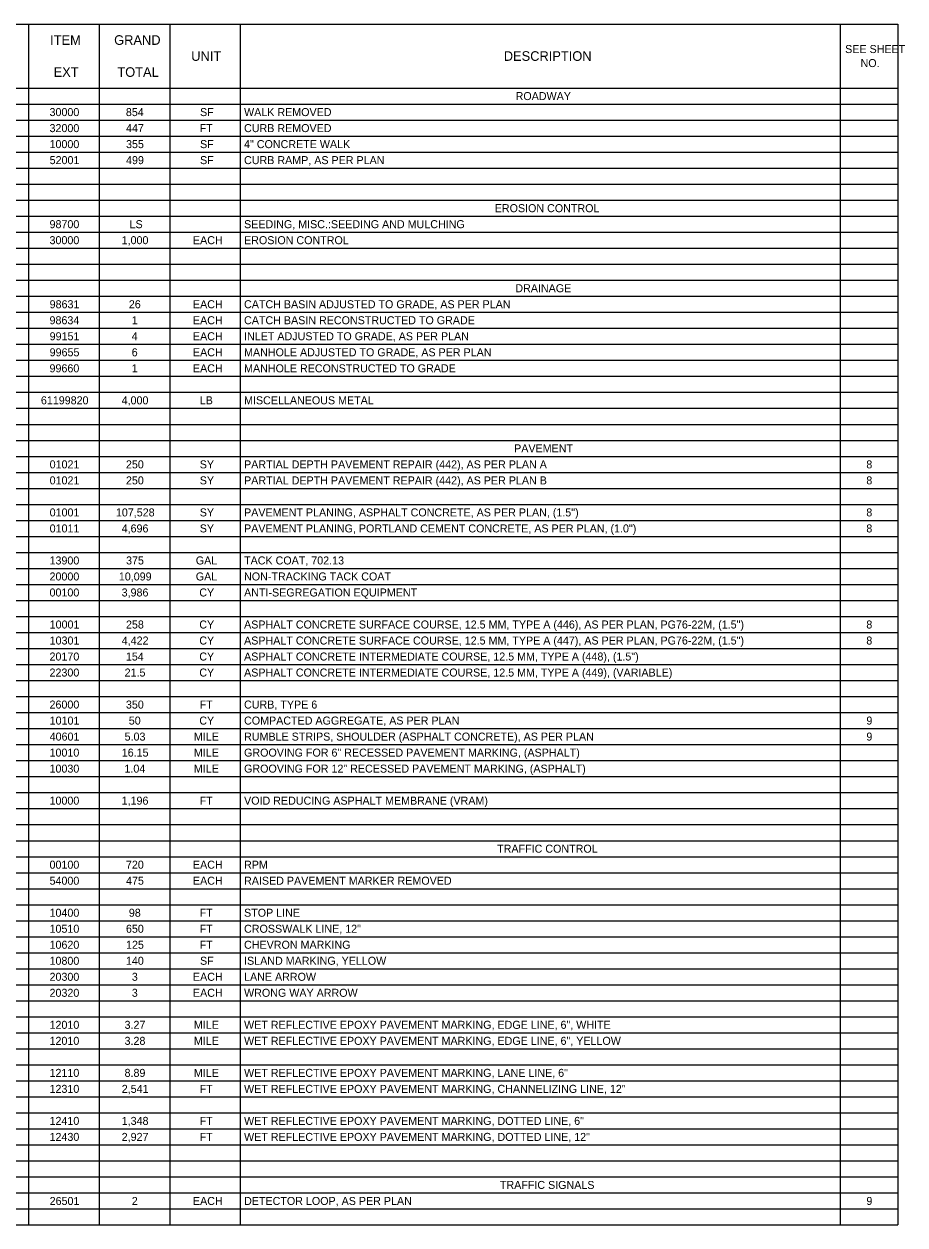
# Model space of a CAD drawing. Extents: x -32.9 to 34, y 0 to 22.
# Drawn here: x -17.72 to -2.31, y 0.5 to 21.5 of the extents above; entities that cross this region are included whole.
import ezdxf

# ---------------------------------------------------------------- set-up
doc = ezdxf.new("R2010")
doc.units = 0
doc.layers.add('SH_Text', color=7, linetype='Continuous')

msp = doc.modelspace()

# ---------------------------------------------------------------- linework, layer by layer
at = {"layer": 'SH_Text'}
for p, q in [((-32.943, 21.5), (-2.439, 21.5)), ((-17.642, 21.5), (-17.642, 0.5)), ((-16.406, 21.5), (-16.406, 0.5)), ((-15.171, 21.5), (-15.171, 0.5)), ((-13.936, 21.5), (-13.936, 0.5)), ((-3.444, 21.5), (-3.444, 0.5)), ((-2.439, 21.5), (-2.439, 0.5)), ((-32.943, 20.38), (-2.439, 20.38)), ((-32.943, 20.1), (-2.439, 20.1)), ((-32.943, 19.82), (-2.439, 19.82)), ((-32.943, 19.54), (-2.439, 19.54)), ((-32.943, 19.26), (-2.439, 19.26)), ((-32.943, 18.98), (-2.439, 18.98)), ((-32.943, 18.7), (-2.439, 18.7)), ((-32.943, 18.42), (-2.439, 18.42)), ((-32.943, 18.14), (-2.439, 18.14)), ((-32.943, 17.86), (-2.439, 17.86)), ((-32.943, 17.58), (-2.439, 17.58)), ((-32.943, 17.3), (-2.439, 17.3)), ((-32.943, 17.02), (-2.439, 17.02)), ((-32.943, 16.74), (-2.439, 16.74)), ((-32.943, 16.46), (-2.439, 16.46)), ((-32.943, 16.18), (-2.439, 16.18)), ((-32.943, 15.9), (-2.439, 15.9)), ((-32.943, 15.62), (-2.439, 15.62)), ((-32.943, 15.34), (-2.439, 15.34)), ((-32.943, 15.06), (-2.439, 15.06)), ((-32.943, 14.78), (-2.439, 14.78)), ((-32.943, 14.5), (-2.439, 14.5)), ((-32.943, 14.22), (-2.439, 14.22)), ((-32.943, 13.94), (-2.439, 13.94)), ((-32.943, 13.66), (-2.439, 13.66)), ((-32.943, 13.38), (-2.439, 13.38)), ((-32.943, 13.1), (-2.439, 13.1)), ((-32.943, 12.82), (-2.439, 12.82)), ((-32.943, 12.54), (-2.439, 12.54)), ((-32.943, 12.26), (-2.439, 12.26)), ((-32.943, 11.98), (-2.439, 11.98)), ((-32.943, 11.7), (-2.439, 11.7)), ((-32.943, 11.42), (-2.439, 11.42)), ((-32.943, 11.14), (-2.439, 11.14)), ((-32.943, 10.86), (-2.439, 10.86)), ((-32.943, 10.58), (-2.439, 10.58)), ((-32.943, 10.3), (-2.439, 10.3)), ((-32.943, 10.02), (-2.439, 10.02)), ((-32.943, 9.74), (-2.439, 9.74)), ((-32.943, 9.46), (-2.439, 9.46)), ((-32.943, 9.18), (-2.439, 9.18)), ((-32.943, 8.9), (-2.439, 8.9)), ((-32.943, 8.62), (-2.439, 8.62)), ((-32.943, 8.34), (-2.439, 8.34)), ((-32.943, 8.06), (-2.439, 8.06)), ((-32.943, 7.78), (-2.439, 7.78)), ((-32.943, 7.5), (-2.439, 7.5)), ((-32.943, 7.22), (-2.439, 7.22)), ((-32.943, 6.94), (-2.439, 6.94)), ((-32.943, 6.66), (-2.439, 6.66)), ((-32.943, 6.38), (-2.439, 6.38)), ((-32.943, 6.1), (-2.439, 6.1)), ((-32.943, 5.82), (-2.439, 5.82)), ((-32.943, 5.54), (-2.439, 5.54)), ((-32.943, 5.26), (-2.439, 5.26)), ((-32.943, 4.98), (-2.439, 4.98)), ((-32.943, 4.7), (-2.439, 4.7)), ((-32.943, 4.42), (-2.439, 4.42)), ((-32.943, 4.14), (-2.439, 4.14)), ((-32.943, 3.86), (-2.439, 3.86)), ((-32.943, 3.58), (-2.439, 3.58)), ((-32.943, 3.3), (-2.439, 3.3)), ((-32.943, 3.02), (-2.439, 3.02)), ((-32.943, 2.74), (-2.439, 2.74)), ((-32.943, 2.46), (-2.439, 2.46)), ((-32.943, 2.18), (-2.439, 2.18)), ((-32.943, 1.9), (-2.439, 1.9)), ((-32.943, 1.62), (-2.439, 1.62)), ((-32.943, 1.34), (-2.439, 1.34)), ((-32.943, 1.06), (-2.439, 1.06)), ((-32.943, 0.78), (-2.439, 0.78)), ((-32.943, 0.5), (-2.439, 0.5))]:
    msp.add_line(p, q, dxfattribs=at)

# ---------------------------------------------------------------- texts
for s, height, p in [('ITEM', 0.168, (-17.262, 21.136)), ('GRAND', 0.168, (-16.142, 21.136)), ('UNIT', 0.168, (-14.794, 20.856)), ('DESCRIPTION', 0.168, (-9.328, 20.856)), ('SEE SHEET ', 0.14, (-3.358, 20.992)), ('NO.', 0.14, (-3.089, 20.747)), ('EXT', 0.168, (-17.201, 20.576)), ('TOTAL', 0.168, (-16.086, 20.576)), ('ROADWAY', 0.14, (-9.121, 20.17)), ('30000', 0.14, (-17.272, 19.89)), ('854', 0.14, (-15.937, 19.89)), ('SF', 0.14, (-14.64, 19.89)), ('WALK REMOVED', 0.14, (-13.87, 19.89)), ('32000', 0.14, (-17.272, 19.61)), ('447', 0.14, (-15.935, 19.61)), ('FT', 0.14, (-14.647, 19.61)), ('CURB REMOVED', 0.14, (-13.87, 19.61)), ('10000', 0.14, (-17.272, 19.33)), ('355', 0.14, (-15.934, 19.33)), ('SF', 0.14, (-14.64, 19.33)), ('4" CONCRETE WALK', 0.14, (-13.87, 19.33)), ('52001', 0.14, (-17.27, 19.05)), ('499', 0.14, (-15.934, 19.05)), ('SF', 0.14, (-14.64, 19.05)), ('CURB RAMP, AS PER PLAN', 0.14, (-13.87, 19.05)), ('EROSION CONTROL', 0.14, (-9.486, 18.21)), ('98700', 0.14, (-17.272, 17.93)), ('LS', 0.14, (-15.872, 17.93)), ('SEEDING, MISC.:SEEDING AND MULCHING', 0.14, (-13.87, 17.93)), ('30000', 0.14, (-17.272, 17.65)), ('1,000', 0.14, (-16.011, 17.65)), ('EACH', 0.14, (-14.764, 17.65)), ('EROSION CONTROL', 0.14, (-13.87, 17.65)), ('DRAINAGE', 0.14, (-9.126, 16.81)), ('98631', 0.14, (-17.27, 16.53)), ('26', 0.14, (-15.885, 16.53)), ('EACH', 0.14, (-14.764, 16.53)), ('CATCH BASIN ADJUSTED TO GRADE, AS PER PLAN', 0.14, (-13.87, 16.53)), ('98634', 0.14, (-17.272, 16.25)), ('1', 0.14, (-15.834, 16.25)), ('EACH', 0.14, (-14.764, 16.25)), ('CATCH BASIN RECONSTRUCTED TO GRADE', 0.14, (-13.87, 16.25)), ('99151', 0.14, (-17.27, 15.97)), ('4', 0.14, (-15.836, 15.97)), ('EACH', 0.14, (-14.764, 15.97)), ('INLET ADJUSTED TO GRADE, AS PER PLAN', 0.14, (-13.87, 15.97)), ('99655', 0.14, (-17.27, 15.69)), ('6', 0.14, (-15.835, 15.69)), ('EACH', 0.14, (-14.764, 15.69)), ('MANHOLE ADJUSTED TO GRADE, AS PER PLAN', 0.14, (-13.87, 15.69)), ('99660', 0.14, (-17.272, 15.41)), ('1', 0.14, (-15.834, 15.41)), ('EACH', 0.14, (-14.764, 15.41)), ('MANHOLE RECONSTRUCTED TO GRADE', 0.14, (-13.87, 15.41)), ('61199820', 0.14, (-17.423, 14.85)), ('4,000', 0.14, (-16.011, 14.85)), ('LB', 0.14, (-14.645, 14.85)), ('MISCELLANEOUS METAL', 0.14, (-13.87, 14.85)), ('PAVEMENT', 0.14, (-9.147, 14.01)), ('01021', 0.14, (-17.27, 13.73)), ('250', 0.14, (-15.936, 13.73)), ('SY', 0.14, (-14.645, 13.73)), ('PARTIAL DEPTH PAVEMENT REPAIR (442), AS PER PLAN A', 0.14, (-13.87, 13.73)), ('8', 0.14, (-2.988, 13.73)), ('01021', 0.14, (-17.27, 13.45)), ('250', 0.14, (-15.936, 13.45)), ('SY', 0.14, (-14.645, 13.45)), ('PARTIAL DEPTH PAVEMENT REPAIR (442), AS PER PLAN B', 0.14, (-13.87, 13.45)), ('8', 0.14, (-2.988, 13.45)), ('01001', 0.14, (-17.27, 12.89)), ('107,528', 0.14, (-16.111, 12.89)), ('SY', 0.14, (-14.645, 12.89)), ('PAVEMENT PLANING, ASPHALT CONCRETE, AS PER PLAN, (1.5")', 0.14, (-13.87, 12.89)), ('8', 0.14, (-2.988, 12.89)), ('01011', 0.14, (-17.27, 12.61)), ('4,696', 0.14, (-16.011, 12.61)), ('SY', 0.14, (-14.645, 12.61)), ('PAVEMENT PLANING, PORTLAND CEMENT CONCRETE, AS PER PLAN, (1.0")', 0.14, (-13.87, 12.61)), ('8', 0.14, (-2.988, 12.61)), ('13900', 0.14, (-17.272, 12.05)), ('375', 0.14, (-15.934, 12.05)), ('GAL', 0.14, (-14.714, 12.05)), ('TACK COAT, 702.13', 0.14, (-13.87, 12.05)), ('20000', 0.14, (-17.272, 11.77)), ('10,099', 0.14, (-16.06, 11.77)), ('GAL', 0.14, (-14.714, 11.77)), ('NON-TRACKING TACK COAT', 0.14, (-13.87, 11.77)), ('00100', 0.14, (-17.272, 11.49)), ('3,986', 0.14, (-16.011, 11.49)), ('CY', 0.14, (-14.653, 11.49)), ('ANTI-SEGREGATION EQUIPMENT', 0.14, (-13.87, 11.49)), ('10001', 0.14, (-17.27, 10.93)), ('258', 0.14, (-15.935, 10.93)), ('CY', 0.14, (-14.653, 10.93)), ('ASPHALT CONCRETE SURFACE COURSE, 12.5 MM, TYPE A (446), AS PER PLAN, PG76-22M, (1.5")', 0.14, (-13.87, 10.93)), ('8', 0.14, (-2.988, 10.93)), ('10301', 0.14, (-17.27, 10.65)), ('4,422', 0.14, (-16.009, 10.65)), ('CY', 0.14, (-14.653, 10.65)), ('ASPHALT CONCRETE SURFACE COURSE, 12.5 MM, TYPE A (447), AS PER PLAN, PG76-22M, (1.5")', 0.14, (-13.87, 10.65)), ('8', 0.14, (-2.988, 10.65)), ('20170', 0.14, (-17.272, 10.37)), ('154', 0.14, (-15.937, 10.37)), ('CY', 0.14, (-14.653, 10.37)), ('ASPHALT CONCRETE INTERMEDIATE COURSE, 12.5 MM, TYPE A (448), (1.5")', 0.14, (-13.87, 10.37)), ('22300', 0.14, (-17.272, 10.09)), ('21.5', 0.14, (-15.959, 10.09)), ('CY', 0.14, (-14.653, 10.09)), ('ASPHALT CONCRETE INTERMEDIATE COURSE, 12.5 MM, TYPE A (449), (VARIABLE)', 0.14, (-13.87, 10.09)), ('26000', 0.14, (-17.272, 9.53)), ('350', 0.14, (-15.936, 9.53)), ('FT', 0.14, (-14.647, 9.53)), ('CURB, TYPE 6', 0.14, (-13.87, 9.53)), ('10101', 0.14, (-17.27, 9.25)), ('50', 0.14, (-15.886, 9.25)), ('CY', 0.14, (-14.653, 9.25)), ('COMPACTED AGGREGATE, AS PER PLAN', 0.14, (-13.87, 9.25)), ('9', 0.14, (-2.987, 9.25)), ('40601', 0.14, (-17.27, 8.97)), ('5.03', 0.14, (-15.959, 8.97)), ('MILE', 0.14, (-14.748, 8.97)), ('RUMBLE STRIPS, SHOULDER (ASPHALT CONCRETE), AS PER PLAN', 0.14, (-13.87, 8.97)), ('9', 0.14, (-2.987, 8.97)), ('10010', 0.14, (-17.272, 8.69)), ('16.15', 0.14, (-16.009, 8.69)), ('MILE', 0.14, (-14.748, 8.69)), ('GROOVING FOR 6" RECESSED PAVEMENT MARKING, (ASPHALT)', 0.14, (-13.87, 8.69)), ('10030', 0.14, (-17.272, 8.41)), ('1.04', 0.14, (-15.962, 8.41)), ('MILE', 0.14, (-14.748, 8.41)), ('GROOVING FOR 12" RECESSED PAVEMENT MARKING, (ASPHALT)', 0.14, (-13.87, 8.41)), ('10000', 0.14, (-17.272, 7.85)), ('1,196', 0.14, (-16.011, 7.85)), ('FT', 0.14, (-14.647, 7.85)), ('VOID REDUCING ASPHALT MEMBRANE (VRAM)', 0.14, (-13.87, 7.85)), ('TRAFFIC CONTROL', 0.14, (-9.444, 7.01)), ('00100', 0.14, (-17.272, 6.73)), ('720', 0.14, (-15.936, 6.73)), ('EACH', 0.14, (-14.764, 6.73)), ('RPM', 0.14, (-13.87, 6.73)), ('54000', 0.14, (-17.272, 6.45)), ('475', 0.14, (-15.934, 6.45)), ('EACH', 0.14, (-14.764, 6.45)), ('RAISED PAVEMENT MARKER REMOVED', 0.14, (-13.87, 6.45)), ('10400', 0.14, (-17.272, 5.89)), ('98', 0.14, (-15.885, 5.89)), ('FT', 0.14, (-14.647, 5.89)), ('STOP LINE', 0.14, (-13.87, 5.89)), ('10510', 0.14, (-17.272, 5.61)), ('650', 0.14, (-15.936, 5.61)), ('FT', 0.14, (-14.647, 5.61)), ('CROSSWALK LINE, 12"', 0.14, (-13.87, 5.61)), ('10620', 0.14, (-17.272, 5.33)), ('125', 0.14, (-15.934, 5.33)), ('FT', 0.14, (-14.647, 5.33)), ('CHEVRON MARKING', 0.14, (-13.87, 5.33)), ('10800', 0.14, (-17.272, 5.05)), ('140', 0.14, (-15.936, 5.05)), ('SF', 0.14, (-14.64, 5.05)), ('ISLAND MARKING, YELLOW', 0.14, (-13.87, 5.05)), ('20300', 0.14, (-17.272, 4.77)), ('3', 0.14, (-15.833, 4.77)), ('EACH', 0.14, (-14.764, 4.77)), ('LANE ARROW', 0.14, (-13.87, 4.77)), ('20320', 0.14, (-17.272, 4.49)), ('3', 0.14, (-15.833, 4.49)), ('EACH', 0.14, (-14.764, 4.49)), ('WRONG WAY ARROW', 0.14, (-13.87, 4.49)), ('12010', 0.14, (-17.272, 3.93)), ('3.27', 0.14, (-15.96, 3.93)), ('MILE', 0.14, (-14.748, 3.93)), ('WET REFLECTIVE EPOXY PAVEMENT MARKING, EDGE LINE, 6", WHITE', 0.14, (-13.87, 3.93)), ('12010', 0.14, (-17.272, 3.65)), ('3.28', 0.14, (-15.96, 3.65)), ('MILE', 0.14, (-14.748, 3.65)), ('WET REFLECTIVE EPOXY PAVEMENT MARKING, EDGE LINE, 6", YELLOW', 0.14, (-13.87, 3.65)), ('12110', 0.14, (-17.272, 3.09)), ('8.89', 0.14, (-15.96, 3.09)), ('MILE', 0.14, (-14.748, 3.09)), ('WET REFLECTIVE EPOXY PAVEMENT MARKING, LANE LINE, 6"', 0.14, (-13.87, 3.09)), ('12310', 0.14, (-17.272, 2.81)), ('2,541', 0.14, (-16.009, 2.81)), ('FT', 0.14, (-14.647, 2.81)), ('WET REFLECTIVE EPOXY PAVEMENT MARKING, CHANNELIZING LINE, 12"', 0.14, (-13.87, 2.81)), ('12410', 0.14, (-17.272, 2.25)), ('1,348', 0.14, (-16.01, 2.25)), ('FT', 0.14, (-14.647, 2.25)), ('WET REFLECTIVE EPOXY PAVEMENT MARKING, DOTTED LINE, 6"', 0.14, (-13.87, 2.25)), ('12430', 0.14, (-17.272, 1.97)), ('2,927', 0.14, (-16.01, 1.97)), ('FT', 0.14, (-14.647, 1.97)), ('WET REFLECTIVE EPOXY PAVEMENT MARKING, DOTTED LINE, 12"', 0.14, (-13.87, 1.97)), ('TRAFFIC SIGNALS', 0.14, (-9.396, 1.13)), ('26501', 0.14, (-17.27, 0.85)), ('2', 0.14, (-15.833, 0.85)), ('EACH', 0.14, (-14.764, 0.85)), ('DETECTOR LOOP, AS PER PLAN', 0.14, (-13.87, 0.85)), ('9', 0.14, (-2.987, 0.85))]:
    msp.add_text(s, height=height, dxfattribs=at).set_placement(p)

doc.saveas('drawing.dxf')
